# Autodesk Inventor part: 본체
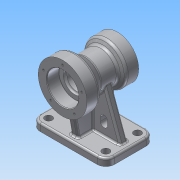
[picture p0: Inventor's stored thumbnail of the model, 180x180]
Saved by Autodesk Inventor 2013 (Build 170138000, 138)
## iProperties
Created: 2015-08
Part Number: 본체
Material: 알루미늄 6061
Document SubType Name: Modeling
Designer: Administrator
Density: 2.71 g/cm^3
Mass: 1062.79 g
Surface Area: 749.652 cm^2
Volume: 392.172 cm^3
Author: Administrator
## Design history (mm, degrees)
sketch "스케치1"
  geometry: L1 (-47, 40)-(47, 40); L2 (61, 26)-(61, -26); L3 (47, -40)-(-47, -40); L4 (-61, -26)-(-61, 26); A1 r 14 centre (47, -26) between (47, -40) and (61, -26); A2 r 14 centre (47, 26) between (61, 26) and (47, 40); A3 r 14 centre (-47, 26) between (-47, 40) and (-61, 26); A4 r 14 centre (-47, -26) between (-61, -26) and (-47, -40); 6 further points
  constraints: 8 end point, 8 point on circle, 8 tangent, 6 point on line, 4 centre point, 2 midpoint, 2 parallel, 1 horizontal, 1 horizontal alignment, 1 perpendicular, 1 vertical alignment
  dimensions: "d0" = 122 distance of point (-61, 40) point (61, 40); "d2" = 80 distance of point (61, 40) point (61, -40); "d3" = 14 radius of A1; "d4" = 14 radius of A2; "d5" = 14 radius of A3; "d6" = 14 radius of A4
extrude "돌출1" new body sketch "스케치1" distance "d7" = 12; taper "d8" = 0 deg
node "작업 평면2"
sketch "스케치4"
  geometry: L1 (47, 40)-(-47, 40) reference; L2 (0, 40)-(0, -50); L3 (0, 40)-(35, 40); L4 (35, 40)-(35, 20); L5 (35, 20)-(26, 14.804); L6 (26, 14.804)-(26, -13.315); L7 (26, -13.315)-(40, -30); L8 (40, -30)-(40, -50); L9 (40, -50)-(0, -50); 1 further point
  constraints: 16 end point, 3 perpendicular, 2 parallel, 1 midpoint, 1 point on line
  dimensions: "d28" = 90 distance of L2.start L2.end; "d31" = 60 deg angle of L5 L6; "d33" = 40 deg angle of L6 L7; "d35" = 20 distance of L3.end L4.end; "d36" = 20 distance of L7.end L8.end; "d38" = 80 diameter of L8 L2; "d39" = 70 diameter of L4 L2; "d40" = 52 diameter of L6 L2
revolve "회전1" sketch "스케치4" stored, may be unused: angle "d41" = 90 deg
sketch "스케치6"
  geometry: L1 (47, 12)-(-47, 12) reference; L2 (-47, 12)-(-61, 12) reference; L3 (61, 12)-(47, 12) reference; L4 (-25.091, 83.185)-(-51, 12); L5 (25.091, 83.185)-(51, 12); L6 (61, 0)-(61, 12) reference; L7 (-61, 0)-(-61, 12) reference; L8 (-51, 12)-(51, 12); A1 r 26 centre (0, 90) between (-25.091, 83.185) and (25.091, 83.185) reference; A2 r 26 centre (0, 90) between (-25.091, 83.185) and (25.091, 83.185); 1 further point
  constraints: 6 end point, 4 point on circle, 2 point on line, 1 centre point, 1 coincident, 1 perpendicular
  dimensions: "d45" = 10 distance from line of L6 L5.end; "d46" = 10 distance from line of L4.end L7; "d47" = 70 deg angle of L5 L1; "d48" = 70 deg angle of L4 L1
extrude "돌출2" join sketch "스케치6" stored distance "d49" = 12; taper "d50" = 0 deg
sketch "스케치8"
  geometry: L1 (26, 12)-(-26, 12) reference; L2 (-26, 12)-(-40, 12) reference; L3 (40, 12)-(26, 12) reference; L4 (-30, 12)-(-39.698, 67); L5 (-39.698, 67)-(30, 67); L6 (30, 67)-(30, 12); L7 (-40, 0)-(-40, 12) reference; L8 (40, 0)-(40, 12) reference; L9 (-30, 12)-(30, 12); 1 further point
  constraints: 8 end point, 2 point on line, 1 collinear, 1 parallel, 1 perpendicular
  dimensions: "d55" = 10 distance from line of L4.start L7; "d56" = 10 distance between parallel lines of L8 L6; "d57" = 80 deg angle of L4 L1; "d58" = 55 distance between parallel lines of L9 L5
extrude "돌출3" join sketch "스케치8" stored distance "d59" = 12; taper "d60" = 0 deg
sketch "스케치9"
  geometry: L1 (-50, 130)-(-50, 50) reference; L2 (40, 125)-(40, 55) reference; L3 (-50, 90)-(40, 90); L4 (-50, 64)-(-30, 64); L5 (-30, 64)-(-30, 71); L6 (-30, 71)-(-27, 71); L7 (-27, 71)-(-27, 74); L8 (-27, 74)-(23, 74); L9 (23, 74)-(23, 70); L10 (23, 70)-(40, 70); 1 further point
  constraints: 16 end point, 4 perpendicular, 3 parallel, 2 midpoint, 2 point on line
  dimensions: "d61" = 52 diameter of L4 L3; "d64" = 38 diameter of L6 L3; "d65" = 32 diameter of L8 L3; "d66" = 40 diameter of L10 L3; "d67" = 20 distance of L4.start L4.end; "d68" = 3 distance of L5.end L6.end; "d69" = 17 distance of L9.end L10.end
revolve "회전2" sketch "스케치9" stored, may be unused: angle "d70" = 90 deg
sketch "스케치11" dims "d71" = 66
  geometry: C1 r 40 at (0, 0) reference; 3 further points
  constraints: 2 vertical alignment, 1 coincident, 2 other
hole "구멍1" sketch "스케치11" at (0, 33) diameter "d73" = 3.242; stored, may be unused: countersink angle "d77" = 90 deg, drill point angle "d79" = 118 deg; dims "d74" = 10, "d75" = 4, "d76" = 2, "d78" = 13
sketch "스케치12" dims "d83" = 54
  geometry: A1 r 35 centre (0, 0) between (-6, 34.482) and (6, 34.482) reference; 3 further points
  constraints: 2 vertical alignment, 1 coincident, 2 other
hole "구멍2" sketch "스케치12" at (0, -27) diameter "d85" = 3.242; stored, may be unused: countersink angle "d89" = 90 deg, drill point angle "d91" = 118 deg; dims "d86" = 10, "d87" = 4, "d88" = 2, "d90" = 13
sketch "스케치13"
  geometry: L1 (-30, 36)-(-30, 30); L2 (-18, 30)-(-18, 36); L3 (18, 36)-(18, 30); L4 (30, 30)-(30, 36); L5 (-47, 12)-(-61, 12) reference; A1 r 6 centre (-24, 30) between (-30, 30) and (-18, 30); A2 r 6 centre (-24, 36) between (-18, 36) and (-30, 36); A3 r 6 centre (24, 30) between (18, 30) and (30, 30); A4 r 6 centre (24, 36) between (30, 36) and (18, 36); 1 further point
  constraints: 8 end point, 8 point on circle, 8 tangent, 4 centre point, 4 parallel, 2 horizontal alignment, 1 equal radius, 1 vertical
  dimensions: "d95" = 12 distance between parallel lines of L4 L3; "d97" = 18 dimension on A3 A4; "d98" = 48 distance of A3.centre A1.centre; "d99" = 24 horizontal distance of A3.centre point (0, 0); "d100" = 18 distance from line of A1.centre L5
extrude "돌출4" cut sketch "스케치13" distance "d101" = 50; taper "d102" = 0 deg
sketch "스케치14"
  geometry: C1 r 6 at (-47, 26); C2 r 6 at (47, 26); C3 r 6 at (47, -26); C4 r 6 at (-47, -26); 1 further point
  constraints: 4 centre point, 3 equal radius, 2 horizontal alignment, 2 vertical alignment
  dimensions: "d103" = 94 distance of C2.centre C1.centre; "d105" = 47 horizontal distance of point (0, 0) C2.centre; "d106" = 52 distance of C3.centre C2.centre; "d107" = 26 vertical distance of C2.centre point (0, 0); "d108" = 12 diameter of C3
extrude "돌출5" cut sketch "스케치14" distance "d109" = 50; taper "d110" = 0 deg
fillet "모깎기1" dims "d111" = 0.3
fillet "모깎기2" dims "d112" = 5
fillet "모깎기3" dims "d113" = 3
fillet "모깎기4" dims "d114" = 3
fillet "모깎기5" dims "d115" = 3
fillet "모깎기6" dims "d116" = 3
fillet "모깎기7" dims "d117" = 3
fillet "모깎기8" dims "d118" = 3
fillet "모깎기9" dims "d119" = 3
fillet "모깎기10" dims "d120" = 3
fillet "모깎기11" dims "d121" = 3
chamfer "모따기1" distance "d122" = 1; stored, may be unused: second distance "d123" = 2, angle "d124" = 45 deg
sketch "스케치16"
  geometry: L1 (15.261, 17.002)-(56.739, 17.002); L2 (56.739, 17.002)-(56.739, 10.998); L3 (56.739, 10.998)-(15.261, 10.998); L4 (15.261, 10.998)-(15.261, 17.002); L5 (12, 37)-(12, 26) reference; L6 (52.119, 30)-(15, 30) reference; 4 further points
  constraints: 2 midpoint, 1 horizontal alignment, 1 parallel, 1 vertical alignment, 2 other
  dimensions: "d125" = 24 distance from line of point (36, 14) L5; "d126" = 16 distance from line of L6 point (36, 14); "d127" = 44.73948 distance between parallel lines of L2 L5; "d128" = 12.99796 distance between parallel lines of L1 L6
feature "엠보싱1" sketch "스케치16" dims "d0" = 122, "d2" = 80, "d3" = 14, "d4" = 14, "d5" = 14, "d6" = 14, "d129" = 0.5, "d130" = 0
node "솔리드1"
pattern_circular "원형 패턴1" dims angle "d81" = 360 deg
pattern_circular "원형 패턴2" dims angle "d93" = 360 deg
